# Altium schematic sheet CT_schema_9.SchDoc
size 147 x 119 mm
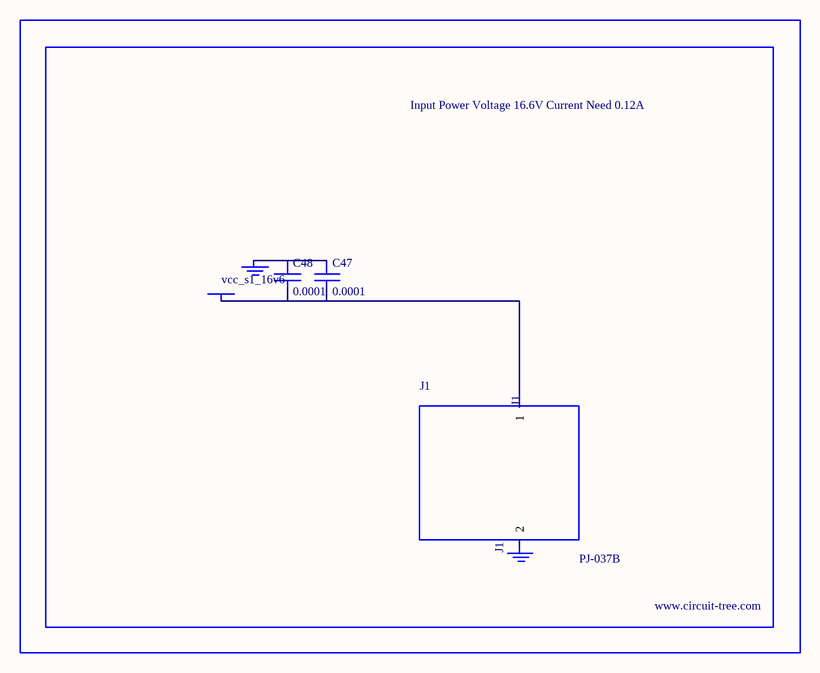
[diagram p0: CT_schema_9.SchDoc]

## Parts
BORDER8  (no value)
C47  0.0001  [EXV-9H]
C48  0.0001  [EXV-9H]
GND_INSTANCE_8_0  (no value)
GND_INSTANCE_8_1  (no value)
J1  PJ-037B  [PJ-037B_PACKAGE]
POWER_INSTANCE_8_0  vcc_s1_16v6

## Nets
NetC47_1: C47.1 C48.1 GND_INSTANCE_8_0.0(GND)
NetC47_2: C47.2 C48.2 J1.1 POWER_INSTANCE_8_0.0(PWR)

Not connected (* = marked no-connect by the designer): GND_INSTANCE_8_1 0(GND); J1 2

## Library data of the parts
BORDER8 = BORDER_PAGE8
C47 C48 = EDK107M035A9HAA
GND_INSTANCE_8_0 GND_INSTANCE_8_1 = GND
POWER_INSTANCE_8_0 = PWR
